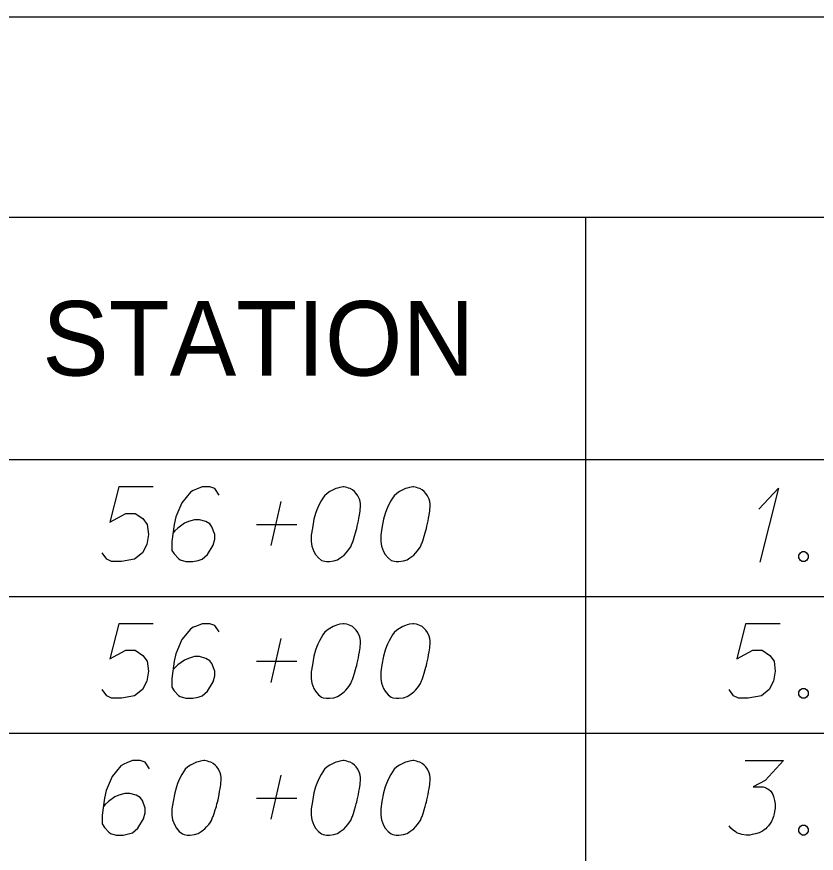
# Model space of a CAD drawing. Extents: x 2074207 to 2076812, y 516372 to 523312.
# Drawn here: x 2076345.6 to 2076397, y 517626.1 to 517679.9 of the extents above; entities that cross this region are included whole.
import ezdxf

# ---------------------------------------------------------------- set-up
doc = ezdxf.new("R2010")
doc.units = 0
for name, color, linetype in [('Prop DirtTable_ Soil Test Results - Outline (Major)', 7, 'Continuous'), ('Prop DirtTable_ Soil Test Results - Outline (Minor)', 7, 'Continuous'), ('Prop DirtTable_ Soil Test Results - Tx (Header - Small)', 7, 'Continuous'), ('Prop DirtTable_ Soil Test Results - Tx (Sample Data)', 7, 'Continuous')]:
    doc.layers.add(name, color=color, linetype=linetype)

msp = doc.modelspace()

# ---------------------------------------------------------------- linework, layer by layer
at = {"layer": 'Prop DirtTable_ Soil Test Results - Outline (Major)'}
for p, q in [((2076260.609, 517679.916), (2076811.903, 517679.916)), ((2076260.609, 517651.43), (2076811.903, 517651.43)), ((2076260.609, 517651.43), (2076811.903, 517651.43))]:
    msp.add_line(p, q, dxfattribs=at)
at = {"layer": 'Prop DirtTable_ Soil Test Results - Outline (Minor)'}
for p, q in [((2076260.609, 517667.03), (2076811.903, 517667.03)), ((2076382.2, 517667.03), (2076382.2, 517642.63)), ((2076260.609, 517642.63), (2076811.903, 517642.63)), ((2076260.609, 517642.63), (2076811.903, 517642.63)), ((2076382.2, 517642.63), (2076382.2, 517633.83)), ((2076260.609, 517633.83), (2076811.903, 517633.83)), ((2076260.609, 517633.83), (2076811.903, 517633.83)), ((2076382.2, 517633.83), (2076382.2, 517625.03))]:
    msp.add_line(p, q, dxfattribs=at)
at = {"layer": 'Prop DirtTable_ Soil Test Results - Tx (Sample Data)'}
for points in [[(2076354.396, 517649.674), (2076352.174, 517649.674), (2076351.609, 517647.406), (2076352.632, 517647.973), (2076353.232, 517647.973), (2076353.726, 517647.633), (2076354.008, 517647.255), (2076354.079, 517646.612), (2076353.973, 517645.97), (2076353.691, 517645.441), (2076353.197, 517645.025), (2076352.35, 517644.874), (2076351.715, 517644.874), (2076351.398, 517645.025), (2076351.116, 517645.441)], [(2076358.629, 517649.145), (2076358.347, 517649.56), (2076358.03, 517649.674), (2076357.536, 517649.674), (2076357.183, 517649.522), (2076356.971, 517649.447), (2076356.795, 517649.333), (2076356.231, 517648.653), (2076355.843, 517647.746), (2076355.737, 517647.255), (2076355.596, 517646.159), (2076355.596, 517645.592), (2076355.737, 517645.365), (2076356.019, 517645.063), (2076356.125, 517644.987), (2076356.478, 517644.874), (2076356.936, 517644.874), (2076357.289, 517644.949), (2076357.536, 517645.025), (2076357.889, 517645.327), (2076358.241, 517645.932), (2076358.347, 517646.31), (2076358.347, 517646.612), (2076358.171, 517647.104), (2076358.03, 517647.293), (2076357.783, 517647.444), (2076357.359, 517647.557), (2076357.042, 517647.557), (2076356.654, 517647.444), (2076356.407, 517647.33), (2076355.984, 517647.028), (2076355.772, 517646.839), (2076355.666, 517646.726)], [(2076366.672, 517649.674), (2076366.602, 517649.674), (2076366.39, 517649.636), (2076366.249, 517649.598), (2076366.143, 517649.56), (2076365.967, 517649.485), (2076365.755, 517649.371), (2076365.579, 517649.258), (2076365.402, 517649.107), (2076365.296, 517648.956), (2076365.191, 517648.767), (2076365.085, 517648.578), (2076364.979, 517648.351), (2076364.908, 517648.2), (2076364.838, 517647.973), (2076364.732, 517647.595), (2076364.626, 517647.028), (2076364.556, 517646.574), (2076364.556, 517646.159), (2076364.591, 517645.856), (2076364.732, 517645.516), (2076364.838, 517645.327), (2076365.014, 517645.1), (2076365.226, 517644.949), (2076365.332, 517644.911), (2076365.543, 517644.874), (2076365.72, 517644.874), (2076366.002, 517644.911), (2076366.249, 517644.987), (2076366.425, 517645.1), (2076366.672, 517645.289), (2076366.778, 517645.403), (2076366.919, 517645.554), (2076367.025, 517645.705), (2076367.095, 517645.819), (2076367.166, 517646.008), (2076367.201, 517646.083), (2076367.272, 517646.272), (2076367.342, 517646.499), (2076367.413, 517646.726), (2076367.448, 517646.877), (2076367.483, 517646.99), (2076367.519, 517647.141), (2076367.589, 517647.482), (2076367.625, 517647.67), (2076367.66, 517647.859), (2076367.695, 517648.124), (2076367.73, 517648.464), (2076367.73, 517648.578), (2076367.695, 517648.729), (2076367.66, 517648.88), (2076367.554, 517649.107), (2076367.448, 517649.258), (2076367.342, 517649.371), (2076367.201, 517649.485), (2076367.06, 517649.56), (2076366.954, 517649.598), (2076366.849, 517649.636), (2076366.672, 517649.674)], [(2076371.152, 517649.674), (2076371.082, 517649.674), (2076370.87, 517649.636), (2076370.729, 517649.598), (2076370.623, 517649.56), (2076370.447, 517649.485), (2076370.235, 517649.371), (2076370.059, 517649.258), (2076369.882, 517649.107), (2076369.776, 517648.956), (2076369.671, 517648.767), (2076369.565, 517648.578), (2076369.459, 517648.351), (2076369.388, 517648.2), (2076369.318, 517647.973), (2076369.212, 517647.595), (2076369.106, 517647.028), (2076369.036, 517646.574), (2076369.036, 517646.159), (2076369.071, 517645.856), (2076369.212, 517645.516), (2076369.318, 517645.327), (2076369.494, 517645.1), (2076369.706, 517644.949), (2076369.812, 517644.911), (2076370.023, 517644.874), (2076370.2, 517644.874), (2076370.482, 517644.911), (2076370.729, 517644.987), (2076370.905, 517645.1), (2076371.152, 517645.289), (2076371.258, 517645.403), (2076371.399, 517645.554), (2076371.505, 517645.705), (2076371.575, 517645.819), (2076371.646, 517646.008), (2076371.681, 517646.083), (2076371.752, 517646.272), (2076371.822, 517646.499), (2076371.893, 517646.726), (2076371.928, 517646.877), (2076371.963, 517646.99), (2076371.999, 517647.141), (2076372.069, 517647.482), (2076372.105, 517647.67), (2076372.14, 517647.859), (2076372.175, 517648.124), (2076372.21, 517648.464), (2076372.21, 517648.578), (2076372.175, 517648.729), (2076372.14, 517648.88), (2076372.034, 517649.107), (2076371.928, 517649.258), (2076371.822, 517649.371), (2076371.681, 517649.485), (2076371.54, 517649.56), (2076371.434, 517649.598), (2076371.329, 517649.636), (2076371.152, 517649.674)], [(2076393.34, 517648.237), (2076394.61, 517649.598), (2076393.411, 517644.836)], [(2076361.98, 517645.894), (2076362.615, 517648.729)], [(2076361.028, 517647.255), (2076363.638, 517647.255)], [(2076396.127, 517645.516), (2076396.304, 517645.516), (2076396.409, 517645.441), (2076396.515, 517645.289), (2076396.515, 517645.1), (2076396.409, 517644.949), (2076396.304, 517644.874), (2076396.127, 517644.874), (2076396.021, 517644.949), (2076395.916, 517645.1), (2076395.916, 517645.289), (2076396.021, 517645.441), (2076396.127, 517645.516)], [(2076354.396, 517640.874), (2076352.174, 517640.874), (2076351.609, 517638.606), (2076352.632, 517639.173), (2076353.232, 517639.173), (2076353.726, 517638.833), (2076354.008, 517638.455), (2076354.079, 517637.812), (2076353.973, 517637.17), (2076353.691, 517636.641), (2076353.197, 517636.225), (2076352.35, 517636.074), (2076351.715, 517636.074), (2076351.398, 517636.225), (2076351.116, 517636.641)], [(2076358.629, 517640.345), (2076358.347, 517640.76), (2076358.03, 517640.874), (2076357.536, 517640.874), (2076357.183, 517640.722), (2076356.971, 517640.647), (2076356.795, 517640.533), (2076356.231, 517639.853), (2076355.843, 517638.946), (2076355.737, 517638.455), (2076355.596, 517637.359), (2076355.596, 517636.792), (2076355.737, 517636.565), (2076356.019, 517636.263), (2076356.125, 517636.187), (2076356.478, 517636.074), (2076356.936, 517636.074), (2076357.289, 517636.149), (2076357.536, 517636.225), (2076357.889, 517636.527), (2076358.241, 517637.132), (2076358.347, 517637.51), (2076358.347, 517637.812), (2076358.171, 517638.304), (2076358.03, 517638.493), (2076357.783, 517638.644), (2076357.359, 517638.757), (2076357.042, 517638.757), (2076356.654, 517638.644), (2076356.407, 517638.53), (2076355.984, 517638.228), (2076355.772, 517638.039), (2076355.666, 517637.926)], [(2076366.672, 517640.874), (2076366.602, 517640.874), (2076366.39, 517640.836), (2076366.249, 517640.798), (2076366.143, 517640.76), (2076365.967, 517640.685), (2076365.755, 517640.571), (2076365.579, 517640.458), (2076365.402, 517640.307), (2076365.296, 517640.156), (2076365.191, 517639.967), (2076365.085, 517639.778), (2076364.979, 517639.551), (2076364.908, 517639.4), (2076364.838, 517639.173), (2076364.732, 517638.795), (2076364.626, 517638.228), (2076364.556, 517637.774), (2076364.556, 517637.359), (2076364.591, 517637.056), (2076364.732, 517636.716), (2076364.838, 517636.527), (2076365.014, 517636.3), (2076365.226, 517636.149), (2076365.332, 517636.111), (2076365.543, 517636.074), (2076365.72, 517636.074), (2076366.002, 517636.111), (2076366.249, 517636.187), (2076366.425, 517636.3), (2076366.672, 517636.489), (2076366.778, 517636.603), (2076366.919, 517636.754), (2076367.025, 517636.905), (2076367.095, 517637.019), (2076367.166, 517637.208), (2076367.201, 517637.283), (2076367.272, 517637.472), (2076367.342, 517637.699), (2076367.413, 517637.926), (2076367.448, 517638.077), (2076367.483, 517638.19), (2076367.519, 517638.341), (2076367.589, 517638.682), (2076367.625, 517638.87), (2076367.66, 517639.059), (2076367.695, 517639.324), (2076367.73, 517639.664), (2076367.73, 517639.778), (2076367.695, 517639.929), (2076367.66, 517640.08), (2076367.554, 517640.307), (2076367.448, 517640.458), (2076367.342, 517640.571), (2076367.201, 517640.685), (2076367.06, 517640.76), (2076366.954, 517640.798), (2076366.849, 517640.836), (2076366.672, 517640.874)], [(2076371.152, 517640.874), (2076371.082, 517640.874), (2076370.87, 517640.836), (2076370.729, 517640.798), (2076370.623, 517640.76), (2076370.447, 517640.685), (2076370.235, 517640.571), (2076370.059, 517640.458), (2076369.882, 517640.307), (2076369.776, 517640.156), (2076369.671, 517639.967), (2076369.565, 517639.778), (2076369.459, 517639.551), (2076369.388, 517639.4), (2076369.318, 517639.173), (2076369.212, 517638.795), (2076369.106, 517638.228), (2076369.036, 517637.774), (2076369.036, 517637.359), (2076369.071, 517637.056), (2076369.212, 517636.716), (2076369.318, 517636.527), (2076369.494, 517636.3), (2076369.706, 517636.149), (2076369.812, 517636.111), (2076370.023, 517636.074), (2076370.2, 517636.074), (2076370.482, 517636.111), (2076370.729, 517636.187), (2076370.905, 517636.3), (2076371.152, 517636.489), (2076371.258, 517636.603), (2076371.399, 517636.754), (2076371.505, 517636.905), (2076371.575, 517637.019), (2076371.646, 517637.208), (2076371.681, 517637.283), (2076371.752, 517637.472), (2076371.822, 517637.699), (2076371.893, 517637.926), (2076371.928, 517638.077), (2076371.963, 517638.19), (2076371.999, 517638.341), (2076372.069, 517638.682), (2076372.105, 517638.87), (2076372.14, 517639.059), (2076372.175, 517639.324), (2076372.21, 517639.664), (2076372.21, 517639.778), (2076372.175, 517639.929), (2076372.14, 517640.08), (2076372.034, 517640.307), (2076371.928, 517640.458), (2076371.822, 517640.571), (2076371.681, 517640.685), (2076371.54, 517640.76), (2076371.434, 517640.798), (2076371.329, 517640.836), (2076371.152, 517640.874)], [(2076394.716, 517640.874), (2076392.494, 517640.874), (2076391.929, 517638.606), (2076392.952, 517639.173), (2076393.552, 517639.173), (2076394.046, 517638.833), (2076394.328, 517638.455), (2076394.399, 517637.812), (2076394.293, 517637.17), (2076394.011, 517636.641), (2076393.517, 517636.225), (2076392.67, 517636.074), (2076392.035, 517636.074), (2076391.718, 517636.225), (2076391.436, 517636.641)], [(2076361.98, 517637.094), (2076362.615, 517639.929)], [(2076361.028, 517638.455), (2076363.638, 517638.455)], [(2076396.127, 517636.716), (2076396.304, 517636.716), (2076396.409, 517636.641), (2076396.515, 517636.489), (2076396.515, 517636.3), (2076396.409, 517636.149), (2076396.304, 517636.074), (2076396.127, 517636.074), (2076396.021, 517636.149), (2076395.916, 517636.3), (2076395.916, 517636.489), (2076396.021, 517636.641), (2076396.127, 517636.716)], [(2076354.149, 517631.545), (2076353.867, 517631.96), (2076353.55, 517632.074), (2076353.056, 517632.074), (2076352.703, 517631.922), (2076352.491, 517631.847), (2076352.315, 517631.733), (2076351.751, 517631.053), (2076351.363, 517630.146), (2076351.257, 517629.655), (2076351.116, 517628.559), (2076351.116, 517627.992), (2076351.257, 517627.765), (2076351.539, 517627.463), (2076351.645, 517627.387), (2076351.998, 517627.274), (2076352.456, 517627.274), (2076352.809, 517627.349), (2076353.056, 517627.425), (2076353.409, 517627.727), (2076353.761, 517628.332), (2076353.867, 517628.71), (2076353.867, 517629.012), (2076353.691, 517629.504), (2076353.55, 517629.693), (2076353.303, 517629.844), (2076352.879, 517629.957), (2076352.562, 517629.957), (2076352.174, 517629.844), (2076351.927, 517629.73), (2076351.504, 517629.428), (2076351.292, 517629.239), (2076351.186, 517629.126)], [(2076357.712, 517632.074), (2076357.642, 517632.074), (2076357.43, 517632.036), (2076357.289, 517631.998), (2076357.183, 517631.96), (2076357.007, 517631.885), (2076356.795, 517631.771), (2076356.619, 517631.658), (2076356.442, 517631.507), (2076356.336, 517631.356), (2076356.231, 517631.167), (2076356.125, 517630.978), (2076356.019, 517630.751), (2076355.948, 517630.6), (2076355.878, 517630.373), (2076355.772, 517629.995), (2076355.666, 517629.428), (2076355.596, 517628.974), (2076355.596, 517628.559), (2076355.631, 517628.256), (2076355.772, 517627.916), (2076355.878, 517627.727), (2076356.054, 517627.5), (2076356.266, 517627.349), (2076356.372, 517627.311), (2076356.583, 517627.274), (2076356.76, 517627.274), (2076357.042, 517627.311), (2076357.289, 517627.387), (2076357.465, 517627.5), (2076357.712, 517627.689), (2076357.818, 517627.803), (2076357.959, 517627.954), (2076358.065, 517628.105), (2076358.135, 517628.219), (2076358.206, 517628.408), (2076358.241, 517628.483), (2076358.312, 517628.672), (2076358.382, 517628.899), (2076358.453, 517629.126), (2076358.488, 517629.277), (2076358.523, 517629.39), (2076358.559, 517629.541), (2076358.629, 517629.882), (2076358.665, 517630.07), (2076358.7, 517630.259), (2076358.735, 517630.524), (2076358.77, 517630.864), (2076358.77, 517630.978), (2076358.735, 517631.129), (2076358.7, 517631.28), (2076358.594, 517631.507), (2076358.488, 517631.658), (2076358.382, 517631.771), (2076358.241, 517631.885), (2076358.1, 517631.96), (2076357.994, 517631.998), (2076357.889, 517632.036), (2076357.712, 517632.074)], [(2076366.672, 517632.074), (2076366.602, 517632.074), (2076366.39, 517632.036), (2076366.249, 517631.998), (2076366.143, 517631.96), (2076365.967, 517631.885), (2076365.755, 517631.771), (2076365.579, 517631.658), (2076365.402, 517631.507), (2076365.296, 517631.356), (2076365.191, 517631.167), (2076365.085, 517630.978), (2076364.979, 517630.751), (2076364.908, 517630.6), (2076364.838, 517630.373), (2076364.732, 517629.995), (2076364.626, 517629.428), (2076364.556, 517628.974), (2076364.556, 517628.559), (2076364.591, 517628.256), (2076364.732, 517627.916), (2076364.838, 517627.727), (2076365.014, 517627.5), (2076365.226, 517627.349), (2076365.332, 517627.311), (2076365.543, 517627.274), (2076365.72, 517627.274), (2076366.002, 517627.311), (2076366.249, 517627.387), (2076366.425, 517627.5), (2076366.672, 517627.689), (2076366.778, 517627.803), (2076366.919, 517627.954), (2076367.025, 517628.105), (2076367.095, 517628.219), (2076367.166, 517628.408), (2076367.201, 517628.483), (2076367.272, 517628.672), (2076367.342, 517628.899), (2076367.413, 517629.126), (2076367.448, 517629.277), (2076367.483, 517629.39), (2076367.519, 517629.541), (2076367.589, 517629.882), (2076367.625, 517630.07), (2076367.66, 517630.259), (2076367.695, 517630.524), (2076367.73, 517630.864), (2076367.73, 517630.978), (2076367.695, 517631.129), (2076367.66, 517631.28), (2076367.554, 517631.507), (2076367.448, 517631.658), (2076367.342, 517631.771), (2076367.201, 517631.885), (2076367.06, 517631.96), (2076366.954, 517631.998), (2076366.849, 517632.036), (2076366.672, 517632.074)], [(2076371.152, 517632.074), (2076371.082, 517632.074), (2076370.87, 517632.036), (2076370.729, 517631.998), (2076370.623, 517631.96), (2076370.447, 517631.885), (2076370.235, 517631.771), (2076370.059, 517631.658), (2076369.882, 517631.507), (2076369.776, 517631.356), (2076369.671, 517631.167), (2076369.565, 517630.978), (2076369.459, 517630.751), (2076369.388, 517630.6), (2076369.318, 517630.373), (2076369.212, 517629.995), (2076369.106, 517629.428), (2076369.036, 517628.974), (2076369.036, 517628.559), (2076369.071, 517628.256), (2076369.212, 517627.916), (2076369.318, 517627.727), (2076369.494, 517627.5), (2076369.706, 517627.349), (2076369.812, 517627.311), (2076370.023, 517627.274), (2076370.2, 517627.274), (2076370.482, 517627.311), (2076370.729, 517627.387), (2076370.905, 517627.5), (2076371.152, 517627.689), (2076371.258, 517627.803), (2076371.399, 517627.954), (2076371.505, 517628.105), (2076371.575, 517628.219), (2076371.646, 517628.408), (2076371.681, 517628.483), (2076371.752, 517628.672), (2076371.822, 517628.899), (2076371.893, 517629.126), (2076371.928, 517629.277), (2076371.963, 517629.39), (2076371.999, 517629.541), (2076372.069, 517629.882), (2076372.105, 517630.07), (2076372.14, 517630.259), (2076372.175, 517630.524), (2076372.21, 517630.864), (2076372.21, 517630.978), (2076372.175, 517631.129), (2076372.14, 517631.28), (2076372.034, 517631.507), (2076371.928, 517631.658), (2076371.822, 517631.771), (2076371.681, 517631.885), (2076371.54, 517631.96), (2076371.434, 517631.998), (2076371.329, 517632.036), (2076371.152, 517632.074)], [(2076392.459, 517632.074), (2076394.928, 517632.074), (2076393.764, 517630.789), (2076392.988, 517630.373), (2076393.623, 517630.373), (2076393.764, 517630.335), (2076393.834, 517630.297), (2076393.905, 517630.259), (2076393.975, 517630.222), (2076394.117, 517630.108), (2076394.187, 517629.995), (2076394.258, 517629.882), (2076394.293, 517629.768), (2076394.363, 517629.504), (2076394.399, 517629.277), (2076394.399, 517629.163), (2076394.399, 517629.012), (2076394.363, 517628.785), (2076394.328, 517628.634), (2076394.293, 517628.483), (2076394.258, 517628.37), (2076394.222, 517628.294), (2076394.187, 517628.219), (2076394.152, 517628.143), (2076394.081, 517628.03), (2076393.975, 517627.878), (2076393.87, 517627.765), (2076393.799, 517627.689), (2076393.693, 517627.614), (2076393.587, 517627.538), (2076393.446, 517627.463), (2076393.376, 517627.425), (2076393.129, 517627.349), (2076392.917, 517627.311), (2076392.776, 517627.274), (2076392.529, 517627.274), (2076392.247, 517627.311), (2076392.141, 517627.349), (2076392.035, 517627.387), (2076391.929, 517627.425), (2076391.824, 517627.5), (2076391.718, 517627.576), (2076391.541, 517627.727), (2076391.436, 517627.878)], [(2076361.98, 517628.294), (2076362.615, 517631.129)], [(2076361.028, 517629.655), (2076363.638, 517629.655)], [(2076396.127, 517627.916), (2076396.304, 517627.916), (2076396.409, 517627.841), (2076396.515, 517627.689), (2076396.515, 517627.5), (2076396.409, 517627.349), (2076396.304, 517627.274), (2076396.127, 517627.274), (2076396.021, 517627.349), (2076395.916, 517627.5), (2076395.916, 517627.689), (2076396.021, 517627.841), (2076396.127, 517627.916)]]:
    msp.add_lwpolyline(points, dxfattribs=at)

# ---------------------------------------------------------------- texts
at = {"layer": 'Prop DirtTable_ Soil Test Results - Tx (Header - Small)'}
msp.add_text('STATION', height=4.8, dxfattribs=at).set_placement((2076347.248, 517656.83))

doc.saveas('drawing.dxf')
